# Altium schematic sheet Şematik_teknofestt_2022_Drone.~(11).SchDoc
size A4; SheetNumber: 1; SheetTotal: 1
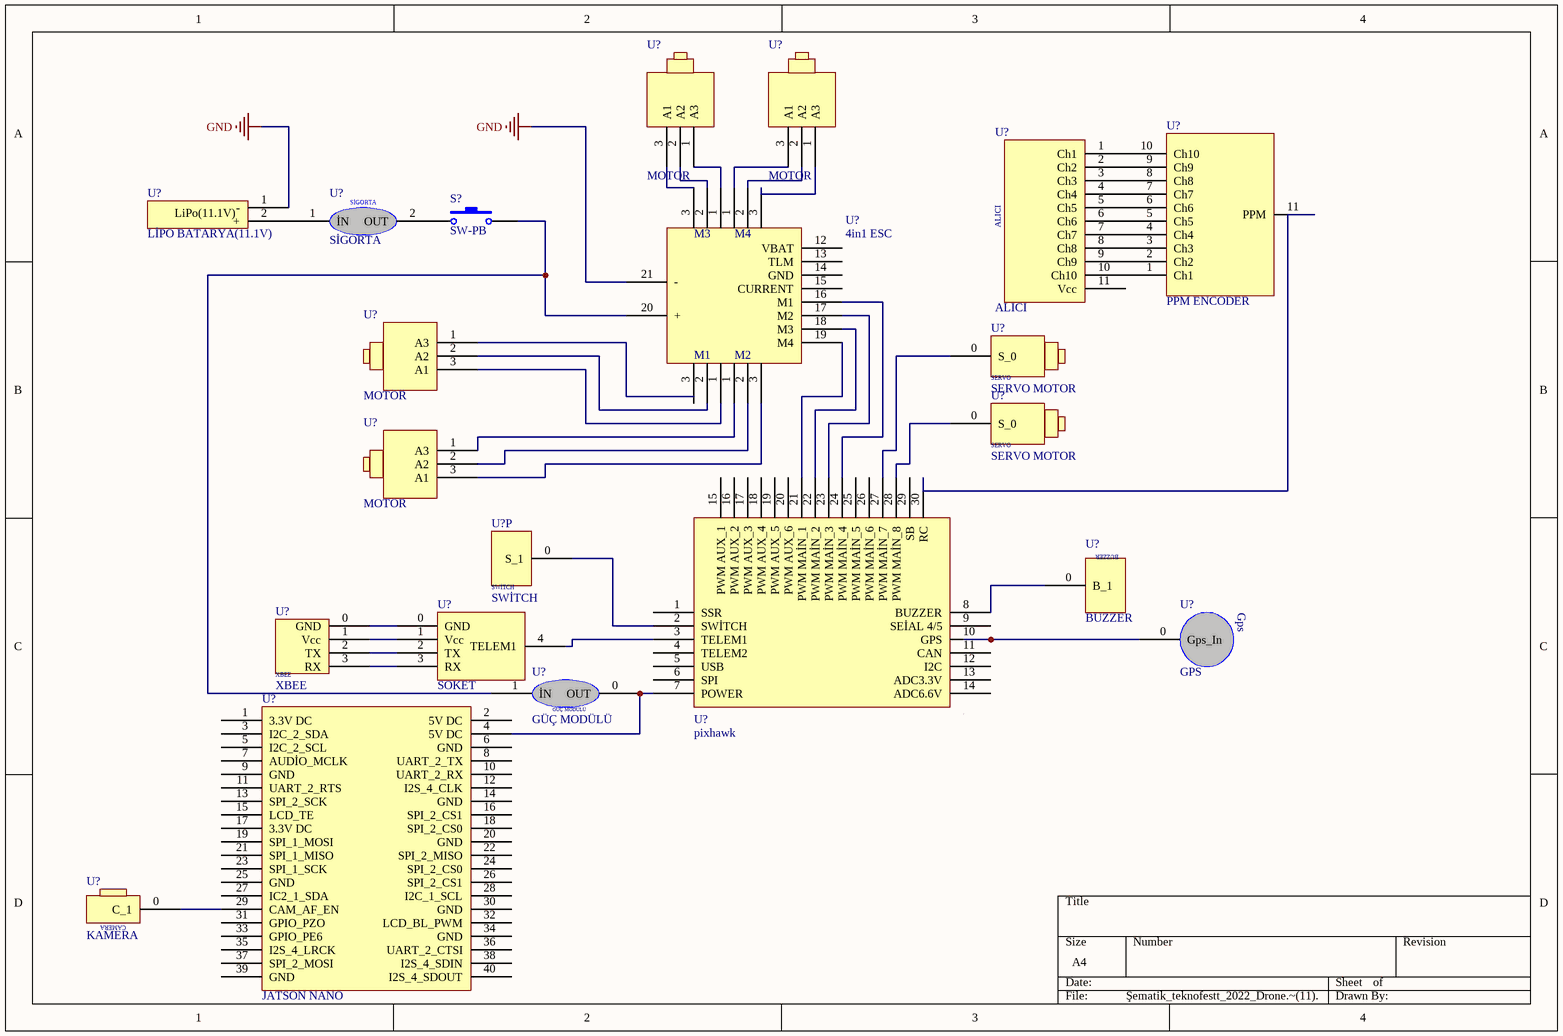
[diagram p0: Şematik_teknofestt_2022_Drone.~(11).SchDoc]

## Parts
(Parts that share a designator on the sheet are numbered #1, #2 ... from top to bottom, then left to right.)
S?  SW-PB  [SPST-2]
U?#1  pixhawk
U?#2  MOTOR
U?#3  MOTOR
U?#4  ALICI
U?#5  LİPO BATARYA(11.1V)
U?#6  SİGORTA
U?#7  4in1 ESC
U?#8  PPM ENCODER
U?#9  MOTOR
U?#10  SERVO MOTOR
U?#11  MOTOR
U?#12  SERVO MOTOR
U?#13  BUZZER
U?#14  GPS
U?#15  XBEE
U?#16  SOKET
U?#17  GÜÇ MODÜLÜ
U?#18  KAMERA
U?#19  JATSON NANO
U?P  SWİTCH

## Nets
 GND: U?#5.1(-) U?#7.21(-)  [also labelled GND]
NetS?_2: S?.2 U?#7.20(+) U?#17.1(İN)
NetU?#1_2: U?#1.2(SWİTCH) U?P.0(S_1)
NetU?#1_3: U?#1.3(TELEM1) U?#16.4(TELEM1)
NetU?#1_7: U?#1.7(POWER) U?#17.0(OUT) U?#19.4(5V_DC)
NetU?#1_8: U?#1.8(BUZZER) U?#13.0(B_1)
NetU?#1_10: U?#1.10(GPS) U?#14.0(Gps_In)
NetU?#1_21: U?#1.21(PWM_MAİN_1) U?#7.19(M4)
NetU?#1_22: U?#1.22(PWM_MAİN_2) U?#7.18(M3)
NetU?#1_23: U?#1.23(PWM_MAİN_3) U?#7.17(M2)
NetU?#1_24: U?#1.24(PWM_MAİN_4) U?#7.16(M1)
NetU?#1_27: U?#1.27(PWM_MAİN_7) U?#10.0(S_0)
NetU?#1_28: U?#1.28(PWM_MAİN_8) U?#12.0(S_0)
NetU?#1_30: U?#1.30(RC) U?#8.11(PPM)
NetU?#2_1: U?#2.1(A3) U?#7.1
NetU?#2_2: U?#2.2(A2) U?#7.2
NetU?#2_3: U?#2.3(A1) U?#7.3
NetU?#3_1: U?#3.1(A3) U?#7.3
NetU?#3_2: U?#3.2(A2) U?#7.2
NetU?#3_3: U?#3.3(A1) U?#7.1
NetU?#4_1: U?#4.1(Ch1) U?#8.10(Ch10)
NetU?#4_2: U?#4.2(Ch2) U?#8.9(Ch9)
NetU?#4_3: U?#4.3(Ch3) U?#8.8(Ch8)
NetU?#4_4: U?#4.4(Ch4) U?#8.7(Ch7)
NetU?#4_5: U?#4.5(Ch5) U?#8.6(Ch6)
NetU?#4_6: U?#4.6(Ch6) U?#8.5(Ch5)
NetU?#4_7: U?#4.7(Ch7) U?#8.4(Ch4)
NetU?#4_8: U?#4.8(Ch8) U?#8.3(Ch3)
NetU?#4_9: U?#4.9(Ch9) U?#8.2(Ch2)
NetU?#4_10: U?#4.10(Ch10) U?#8.1(Ch1)
NetU?#5_2: U?#5.2(+) U?#6.1(İN)
NetU?#7_1: U?#7.1 U?#9.3(A1)
NetU?#7_1: U?#7.1 U?#11.1(A3)  [a separate net that carries the same name]
NetU?#7_2: U?#7.2 U?#9.2(A2)
NetU?#7_2: U?#7.2 U?#11.2(A2)  [a separate net that carries the same name]
NetU?#7_3: U?#7.3 U?#11.3(A1)
NetU?#15_0: U?#15.0(GND) U?#16.0(GND)
NetU?#15_1: U?#15.1(Vcc) U?#16.1(Vcc)
NetU?#15_2: U?#15.2(TX) U?#16.2(TX)
NetU?#15_3: U?#15.3(RX) U?#16.3(RX)
NetU?#18_0: U?#18.0(C_1) U?#19.29(CAM_AF_EN)

Not connected (* = marked no-connect by the designer): S? 1; U?#1 1(SSR) 4(TELEM2) 5(USB) 6(SPI) 9(SEİAL_4/5) 11(CAN) 12(I2C) 13(ADC3.3V) 14(ADC6.6V) 15(PWM_AUX_1) 16(PWM_AUX_2) 17(PWM_AUX_3) 18(PWM_AUX_4) 19(PWM_AUX_5) 20(PWM_AUX_6) 25(PWM_MAİN_5) 26(PWM_MAİN_6) 29(SB); U?#4 11(Vcc); U?#6 2(OUT); U?#7 12(VBAT) 13(TLM) 14(GND) 15(CURRENT); U?#9 1(A3); U?#19 1(3.3V_DC) 2(5V_DC) 3(I2C_2_SDA) 5(I2C_2_SCL) 6(GND) 7(AUDİO_MCLK) 8(UART_2_TX) 9(GND) 10(UART_2_RX) 11(UART_2_RTS) 12(I2S_4_CLK) 13(SPI_2_SCK) 14(GND) 15(LCD_TE) 16(SPI_2_CS1) 17(3.3V_DC) 18(SPI_2_CS0) 19(SPI_1_MOSI) 20(GND) 21(SPI_1_MISO) 22(SPI_2_MISO) 23(SPI_1_SCK) 24(SPI_2_CS0) 25(GND) 26(SPI_2_CS1) 27(IC2_1_SDA) 28(I2C_1_SCL) 30(GND) 31(GPIO_PZO) 32(LCD_BL_PWM) 33(GPIO_PE6) 34(GND) 35(I2S_4_LRCK) 36(UART_2_CTSI) 37(SPI_2_MOSI) 38(I2S_4_SDIN) 39(GND) 40(I2S_4_SDOUT)

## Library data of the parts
S? = SW-PB: Switch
